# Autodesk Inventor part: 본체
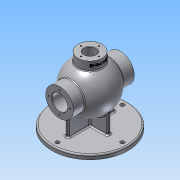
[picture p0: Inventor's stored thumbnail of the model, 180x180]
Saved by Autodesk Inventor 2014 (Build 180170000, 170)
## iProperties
Created: 2020-08
Part Number: 본체
Material: 알루미늄 6061
Document SubType Name: Modeling
Designer: net
Mass: 1759.3 g
Surface Area: 1343.04 cm^2
Volume: 649.187 cm^3
Density: 2.71 g/cm^3
Appearance: 알루미늄 - 평지
Author: net
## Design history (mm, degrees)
sketch "스케치1"
  geometry: L1 (-53, 0)-(53, 0); L2 (-53, 0)-(-43, 0); L3 (43, 0)-(53, 0); A1 r 53 centre (0, 0) between (53, 0) and (-53, 0); A2 r 43 centre (0, 0) between (43, 0) and (-43, 0); 1 further point
  constraints: 6 end point, 4 point on circle, 2 centre point, 2 coincident, 2 collinear, 2 point on line, 1 horizontal, 1 horizontal alignment
  dimensions: "d0" = 53 radius of A1; "d1" = 43 radius of A2
revolve "회전1" sketch "스케치1" stored, may be unused: angle "d2" = 90 deg
sketch "스케치2"
  geometry: L1 (0, 68)-(0, -68); 2 further points
  constraints: 2 end point, 1 coincident, 1 midpoint, 1 vertical
  dimensions: "d3" = 136 distance of L1.start L1.end
node "작업 평면1"
sketch "스케치3"
  geometry: C1 r 31 at (0, 0); 1 further point
  constraints: 1 centre point, 1 coincident
  dimensions: "d5" = 62 diameter of C1
extrude "돌출1" join sketch "스케치3" stored distance "d6" = 10; taper "d7" = 0 deg
sketch "스케치4"
  geometry: L1 (0, 68)-(0, -68); L2 (31, 68)-(31, 42.988) reference; L3 (31, -42.988)-(31, -68) reference; L4 (31, -68)-(-31, -68) reference; L5 (-31, -68)-(-31, -42.988) reference; L6 (-31, 42.988)-(-31, 68) reference; L7 (-31, 68)-(31, 68) reference; L8 (17.5, 68)-(17.5, 52); L9 (17.5, 52)-(18.5, 52); L10 (18.5, 52)-(18.5, 50.25); L11 (18.5, 50.25)-(17.5, 50.25); L12 (17.5, 50.25)-(17.5, -68); L13 (17.5, 68)-(0, 68); L14 (17.5, -68)-(0, -68); A1 r 43 centre (0, 0) between (0, 43) and (0, -43) reference; A2 r 43 centre (0, 0) between (0, -43) and (0, 43) reference; A3 r 53 centre (0, 0) between (31, -42.988) and (31, 42.988) reference; A4 r 53 centre (0, 0) between (-31, 42.988) and (-31, -42.988) reference; 2 further points
  constraints: 16 end point, 4 perpendicular, 3 midpoint, 2 parallel, 2 point on line, 1 coincident, 1 collinear, 1 vertical
  dimensions: "d8" = 35 diameter of L8 L1; "d9" = 16 distance of L8.start L8.end; "d10" = 37 diameter of L10 L1; "d11" = 1.75 distance of L9.end L10.end; "d12" = 35 diameter of L12 L1
revolve "회전2" sketch "스케치4" stored, may be unused: angle "d13" = 90 deg
node "작업 평면2"
sketch "스케치5"
  geometry: C1 r 27 at (0, 0); 1 further point
  constraints: 1 centre point, 1 coincident
  dimensions: "d16" = 54 diameter of C1
extrude "돌출2" join sketch "스케치5" stored distance "d17" = 10; taper "d18" = 0 deg
hole "구멍1" diameter "d21" = 26; stored, may be unused: countersink angle "d25" = 90 deg, drill point angle "d27" = 0 deg; dims "d19" = 10, "d20" = 10, "d22" = 6, "d23" = 4, "d24" = 2, "d26" = 8
sketch "스케치6" dims "d28" = 48
  geometry: C1 r 17.5 at (0, 0) reference; C2 r 31 at (0, 0) reference; 2 further points
  constraints: 2 vertical alignment, 1 coincident, 2 other
hole "구멍2" sketch "스케치6" at (0, 24) diameter "d29" = 3.242; stored, may be unused: countersink angle "d33" = 90 deg, drill point angle "d35" = 118 deg; dims "d30" = 12, "d31" = 4, "d32" = 2, "d34" = 15
sketch "스케치7" dims "d39" = 40
  geometry: C1 r 13 at (0, 0) reference; C2 r 27 at (0, 0) reference; 2 further points
  constraints: 2 vertical alignment, 1 coincident, 2 other
hole "구멍3" sketch "스케치7" at (0, 20) diameter "d40" = 3.242; stored, may be unused: countersink angle "d44" = 90 deg, drill point angle "d46" = 118 deg; dims "d41" = 12, "d42" = 4, "d43" = 2, "d45" = 15
node "작업 평면3"
sketch "스케치8" dims "d52" = 145
  geometry: C1 r 85 at (0, 0); 3 further points
  constraints: 2 coincident, 2 vertical alignment, 1 centre point, 2 other
  dimensions: "d51" = 170 diameter of C1
extrude "돌출3" join sketch "스케치8" distance "d53" = 10; taper "d54" = 0 deg
hole "구멍4" sketch "스케치8" diameter "d55" = 9; stored, may be unused: countersink angle "d59" = 90 deg, drill point angle "d61" = 0 deg; dims "d56" = 12, "d57" = 4, "d58" = 2, "d60" = 15
sketch "스케치9"
  geometry: L1 (-4, 52)-(4, 52); L2 (4, 52)-(4, -52); L3 (4, -52)-(-4, -52); L4 (-4, -52)-(-4, 52); L5 (-43, 4)-(43, 4); L6 (43, 4)-(43, -4); L7 (43, -4)-(-43, -4); L8 (-43, -4)-(-43, 4); C1 r 85 at (0, 0) reference; 4 further points
  constraints: 16 end point, 4 midpoint, 4 parallel, 2 horizontal, 2 horizontal alignment, 2 perpendicular, 2 vertical alignment
  dimensions: "d65" = 8 distance of L1.start L1.end; "d66" = 8 distance of L5.end L6.end; "d67" = 86 distance of L6.end L7.end; "d68" = 104 distance of L1.end L2.end
extrude "돌출4" join sketch "스케치9" stored distance "d69" = 10; taper "d70" = 0 deg
chamfer "모따기1" distance "d71" = 1; stored, may be unused: second distance "d72" = 2, angle "d73" = 45 deg
node "작업 평면4"
fillet "모깎기1" dims "d79" = 3
fillet "모깎기2" dims "d80" = 3
fillet "모깎기3" dims "d81" = 3
chamfer "모따기2" distance "d82" = 1; stored, may be unused: second distance "d83" = 2, angle "d84" = 45 deg
sketch "스케치13"
  geometry: L1 (0, 0)-(-28.393, 0); C1 r 1.621 at (20, 0) reference; C2 r 27 at (0, 0) reference; C3 r 1.621 at (0, -20) reference; C4 r 1.621 at (-20, 0) reference; C5 r 1.621 at (0, 20) reference; C6 r 14 at (0, 0) reference; 1 further point
  constraints: 2 end point, 2 horizontal alignment, 1 other
node "작업 평면8"
sketch "스케치14"
  geometry: L1 (0, -27)-(0, 27) reference; L2 (0, -27)-(17.714, -27) reference; 2 further points
  constraints: 1 other
  dimensions: "d88" = 27 distance from line of L2 point (9, 0); "d89" = 9 distance from line of L1 point (9, 0)
feature "엠보싱2" sketch "스케치14" dims "d0" = 53, "d1" = 43, "d90" = 0.5, "d91" = 0
node "솔리드1"
mirror "대칭1"
pattern_circular "원형 패턴1" dims angle "d37" = 360 deg
mirror "대칭2"
pattern_circular "원형 패턴2" dims angle "d48" = 360 deg
pattern_circular "원형 패턴3" dims angle "d63" = 360 deg
node "절단 모서리 투영1"
other parameters: "d14" = 65, "d50" = -85, "d74" = 27
